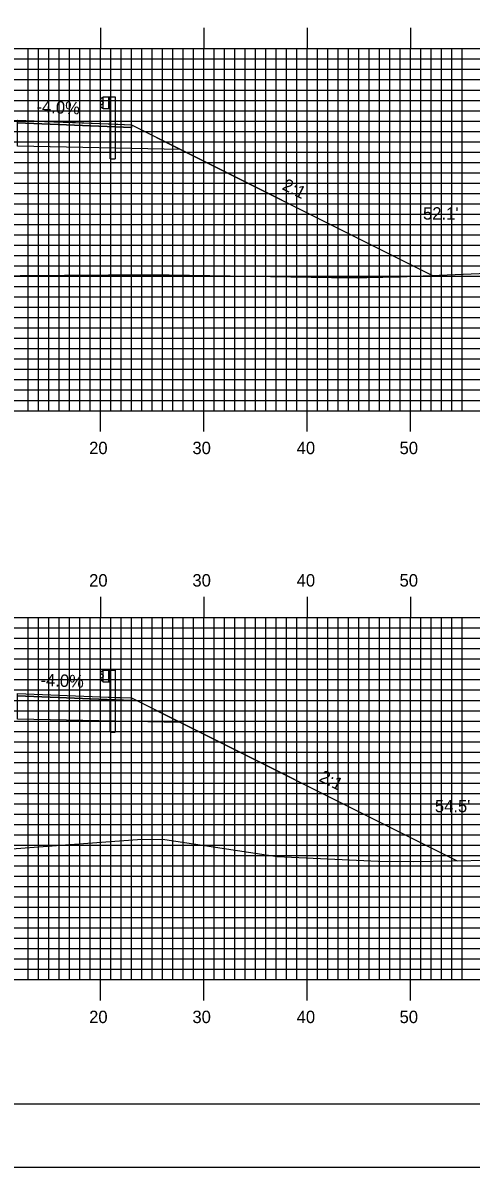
# Model space of a CAD drawing. Extents: x 1760610 to 1760954, y 442591 to 442811.
# Drawn here: x 1760788.7 to 1760832.1, y 442590.5 to 442701.2 of the extents above; entities that cross this region are included whole.
import ezdxf

# ---------------------------------------------------------------- set-up
doc = ezdxf.new("R2010")
doc.units = 0
for name, color, linetype in [('ANNOTATION', 7, 'Continuous'), ('BORDER', 7, 'Continuous'), ('D_Guardrail_Beam_Rt', 7, 'Continuous'), ('D_Roadway_Centerline', 7, 'Continuous'), ('D_Roadway_Edge_Shoulder', 7, 'Continuous'), ('D_Roadway_SlopeLines', 7, 'Continuous'), ('D_Roadway_SubGrade', 7, 'Continuous'), ('D_Text_Standard', 7, 'Continuous'), ('H_V ANNOTATION', 7, 'Continuous'), ('MAJOR', 7, 'Continuous'), ('MINOR', 7, 'Continuous'), ('PLOT BOUNDARY', 7, 'Continuous'), ('S_Roadway_Centerline', 7, 'Continuous')]:
    doc.layers.add(name, color=color, linetype=linetype)

msp = doc.modelspace()

# ---------------------------------------------------------------- linework, layer by layer
at = {"layer": 'BORDER'}
msp.add_lwpolyline([(1760626.61, 442596.67), (1760946.61, 442596.67), (1760946.61, 442806.67), (1760626.61, 442806.67)], close=True, dxfattribs=at)
at = {"layer": 'D_Guardrail_Beam_Rt'}
for p, q in [((1760796.39, 442693.91), (1760796.25, 442693.81)), ((1760796.48, 442693.93), (1760796.41, 442693.91)), ((1760796.48, 442694.01), (1760797.17, 442694.01)), ((1760796.48, 442692.84), (1760796.48, 442694.01)), ((1760797.01, 442694.01), (1760797.01, 442692.84)), ((1760797.11, 442694.01), (1760797.11, 442692.84)), ((1760797.17, 442694.01), (1760797.64, 442694.01)), ((1760797.17, 442694.01), (1760797.17, 442692.84)), ((1760797.64, 442694.01), (1760797.64, 442688.01)), ((1760796.25, 442693.66), (1760796.45, 442693.53)), ((1760796.45, 442693.33), (1760796.25, 442693.19)), ((1760796.25, 442693.05), (1760796.39, 442692.95)), ((1760796.41, 442692.94), (1760796.48, 442692.93)), ((1760796.48, 442693.46), (1760796.48, 442693.39)), ((1760797.17, 442692.84), (1760796.48, 442692.84)), ((1760797.15, 442688.01), (1760797.15, 442692.84)), ((1760797.15, 442688.01), (1760797.64, 442688.01)), ((1760796.39, 442638.5), (1760796.25, 442638.4)), ((1760796.48, 442638.52), (1760796.41, 442638.51)), ((1760796.48, 442638.6), (1760797.17, 442638.6)), ((1760796.48, 442637.44), (1760796.48, 442638.6)), ((1760797.01, 442638.6), (1760797.01, 442637.44)), ((1760797.11, 442638.6), (1760797.11, 442637.44)), ((1760797.17, 442638.6), (1760797.64, 442638.6)), ((1760797.17, 442638.6), (1760797.17, 442637.44)), ((1760797.64, 442638.6), (1760797.64, 442632.6)), ((1760796.25, 442638.26), (1760796.45, 442638.12)), ((1760796.45, 442637.92), (1760796.25, 442637.79)), ((1760796.25, 442637.64), (1760796.39, 442637.54)), ((1760796.41, 442637.54), (1760796.48, 442637.52)), ((1760796.48, 442638.06), (1760796.48, 442637.99)), ((1760797.17, 442637.44), (1760796.48, 442637.44)), ((1760797.15, 442632.6), (1760797.15, 442637.44)), ((1760797.15, 442632.6), (1760797.64, 442632.6))]:
    msp.add_line(p, q, dxfattribs=at)
for centre, major_axis, start_param, end_param in [((1760796.3, 442693.73), (-0.0877, 0), 5.323254, 7.243116), ((1760796.42, 442693.87), (-0.0417, 0), 4.907132, 5.323254), ((1760796.3, 442693.12), (-0.0877, 0), 5.323254, 7.243116), ((1760796.42, 442692.98), (-0.0417, 0), 0.959931, 1.376053), ((1760796.4, 442693.46), (0.0789, 0), 0, 0.959931), ((1760796.4, 442693.39), (0.0789, 0), 5.323254, 6.283185), ((1760796.42, 442638.47), (-0.0417, 0), 4.907132, 5.323254), ((1760796.3, 442638.33), (-0.0877, 0), 5.323254, 7.243116), ((1760796.3, 442637.71), (-0.0877, 0), 5.323254, 7.243116), ((1760796.42, 442637.58), (-0.0417, 0), 0.959931, 1.376053), ((1760796.4, 442638.06), (0.0789, 0), 0, 0.959931), ((1760796.4, 442637.99), (0.0789, 0), 5.323254, 6.283185)]:
    msp.add_ellipse(centre, major_axis=major_axis, ratio=0.995501, start_param=start_param, end_param=end_param, dxfattribs=at)
at = {"layer": 'D_Roadway_Centerline'}
for points in [[(1760723.62, 442675.65), (1760747.92, 442687.8), (1760747.92, 442687.8), (1760749.52, 442688.6), (1760753.21, 442690.44), (1760753.22, 442690.44), (1760756.21, 442690.56), (1760756.22, 442690.56), (1760764.21, 442690.88), (1760764.23, 442690.88), (1760769.08, 442691.06), (1760776.21, 442691.32), (1760776.21, 442691.32), (1760784.04, 442691.6), (1760788.21, 442691.75), (1760788.22, 442691.75), (1760790.81, 442691.64), (1760796.21, 442691.43), (1760796.21, 442691.43), (1760797.9, 442691.36), (1760799.21, 442691.31), (1760803.96, 442688.93), (1760828.33, 442676.75), (1760828.33, 442676.75)], [(1760788.21, 442636.34), (1760789.01, 442636.31), (1760796.21, 442636.02), (1760797.7, 442635.96), (1760799.21, 442635.9), (1760803.58, 442633.72), (1760803.96, 442633.53), (1760822.99, 442624.02), (1760830.72, 442620.15)]]:
    msp.add_lwpolyline(points, dxfattribs=at)
at = {"layer": 'D_Roadway_Edge_Shoulder'}
for points in [[(1760788.21, 442691.75), (1760796.21, 442691.43), (1760796.21, 442691.43), (1760799.21, 442691.31), (1760799.21, 442691.06), (1760788.21, 442691.5)], [(1760788.21, 442636.34), (1760796.21, 442636.02), (1760796.21, 442636.02), (1760799.21, 442635.9), (1760799.21, 442635.65), (1760788.21, 442636.09)]]:
    msp.add_lwpolyline(points, close=True, dxfattribs=at)
at = {"layer": 'D_Roadway_SlopeLines'}
for points in [[(1760799.21, 442691.31), (1760828.33, 442676.75)], [(1760799.21, 442635.9), (1760830.72, 442620.15)]]:
    msp.add_lwpolyline(points, dxfattribs=at)
at = {"layer": 'D_Roadway_SubGrade'}
for points in [[(1760788.21, 442691.08), (1760788.21, 442691.5), (1760799.21, 442691.06), (1760799.21, 442691.31), (1760803.96, 442688.93), (1760788.21, 442689.25)], [(1760788.21, 442635.68), (1760788.21, 442636.09), (1760799.21, 442635.65), (1760799.21, 442635.9), (1760803.96, 442633.53), (1760788.21, 442633.84)]]:
    msp.add_lwpolyline(points, close=True, dxfattribs=at)
at = {"layer": 'MAJOR'}
for p, q in [((1760796.21, 442700.67), (1760796.21, 442698.67)), ((1760806.21, 442700.67), (1760806.21, 442698.67)), ((1760816.21, 442700.67), (1760816.21, 442698.67)), ((1760826.21, 442700.67), (1760826.21, 442698.67)), ((1760636.21, 442698.67), (1760916.21, 442698.67)), ((1760636.21, 442698.67), (1760916.21, 442698.67)), ((1760796.21, 442663.67), (1760796.21, 442698.67)), ((1760806.21, 442663.67), (1760806.21, 442698.67)), ((1760816.21, 442663.67), (1760816.21, 442698.67)), ((1760826.21, 442663.67), (1760826.21, 442698.67)), ((1760636.21, 442693.67), (1760916.21, 442693.67)), ((1760636.21, 442688.67), (1760916.21, 442688.67)), ((1760636.21, 442683.67), (1760916.21, 442683.67)), ((1760636.21, 442678.67), (1760916.21, 442678.67)), ((1760636.21, 442673.67), (1760916.21, 442673.67)), ((1760636.21, 442668.67), (1760916.21, 442668.67)), ((1760636.21, 442663.67), (1760916.21, 442663.67)), ((1760636.21, 442663.67), (1760916.21, 442663.67)), ((1760796.21, 442661.66), (1760796.21, 442663.67)), ((1760806.21, 442661.66), (1760806.21, 442663.67)), ((1760816.21, 442661.66), (1760816.21, 442663.67)), ((1760826.21, 442661.66), (1760826.21, 442663.67)), ((1760796.21, 442645.67), (1760796.21, 442643.67)), ((1760806.21, 442645.67), (1760806.21, 442643.67)), ((1760816.21, 442645.67), (1760816.21, 442643.67)), ((1760826.21, 442645.67), (1760826.21, 442643.67)), ((1760636.21, 442643.67), (1760916.21, 442643.67)), ((1760636.21, 442643.67), (1760916.21, 442643.67)), ((1760796.21, 442608.67), (1760796.21, 442643.67)), ((1760806.21, 442608.67), (1760806.21, 442643.67)), ((1760816.21, 442608.67), (1760816.21, 442643.67)), ((1760826.21, 442608.67), (1760826.21, 442643.67)), ((1760636.21, 442638.67), (1760916.21, 442638.67)), ((1760636.21, 442633.67), (1760916.21, 442633.67)), ((1760636.21, 442628.67), (1760916.21, 442628.67)), ((1760636.21, 442623.67), (1760916.21, 442623.67)), ((1760636.21, 442618.67), (1760916.21, 442618.67)), ((1760636.21, 442613.67), (1760916.21, 442613.67)), ((1760636.21, 442608.67), (1760916.21, 442608.67)), ((1760636.21, 442608.67), (1760916.21, 442608.67)), ((1760796.21, 442606.66), (1760796.21, 442608.67)), ((1760806.21, 442606.66), (1760806.21, 442608.67)), ((1760816.21, 442606.66), (1760816.21, 442608.67)), ((1760826.21, 442606.66), (1760826.21, 442608.67))]:
    msp.add_line(p, q, dxfattribs=at)
at = {"layer": 'MINOR'}
for p, q in [((1760789.21, 442663.67), (1760789.21, 442698.67)), ((1760790.21, 442663.67), (1760790.21, 442698.67)), ((1760791.21, 442663.67), (1760791.21, 442698.67)), ((1760792.21, 442663.67), (1760792.21, 442698.67)), ((1760793.21, 442663.67), (1760793.21, 442698.67)), ((1760794.21, 442663.67), (1760794.21, 442698.67)), ((1760795.21, 442663.67), (1760795.21, 442698.67)), ((1760797.21, 442663.67), (1760797.21, 442698.67)), ((1760798.21, 442663.67), (1760798.21, 442698.67)), ((1760799.21, 442663.67), (1760799.21, 442698.67)), ((1760800.21, 442663.67), (1760800.21, 442698.67)), ((1760801.21, 442663.67), (1760801.21, 442698.67)), ((1760802.21, 442663.67), (1760802.21, 442698.67)), ((1760803.21, 442663.67), (1760803.21, 442698.67)), ((1760804.21, 442663.67), (1760804.21, 442698.67)), ((1760805.21, 442663.67), (1760805.21, 442698.67)), ((1760807.21, 442663.67), (1760807.21, 442698.67)), ((1760808.21, 442663.67), (1760808.21, 442698.67)), ((1760809.21, 442663.67), (1760809.21, 442698.67)), ((1760810.21, 442663.67), (1760810.21, 442698.67)), ((1760811.21, 442663.67), (1760811.21, 442698.67)), ((1760812.21, 442663.67), (1760812.21, 442698.67)), ((1760813.21, 442663.67), (1760813.21, 442698.67)), ((1760814.21, 442663.67), (1760814.21, 442698.67)), ((1760815.21, 442663.67), (1760815.21, 442698.67)), ((1760817.21, 442663.67), (1760817.21, 442698.67)), ((1760818.21, 442663.67), (1760818.21, 442698.67)), ((1760819.21, 442663.67), (1760819.21, 442698.67)), ((1760820.21, 442663.67), (1760820.21, 442698.67)), ((1760821.21, 442663.67), (1760821.21, 442698.67)), ((1760822.21, 442663.67), (1760822.21, 442698.67)), ((1760823.21, 442663.67), (1760823.21, 442698.67)), ((1760824.21, 442663.67), (1760824.21, 442698.67)), ((1760825.21, 442663.67), (1760825.21, 442698.67)), ((1760827.21, 442663.67), (1760827.21, 442698.67)), ((1760828.21, 442663.67), (1760828.21, 442698.67)), ((1760829.21, 442663.67), (1760829.21, 442698.67)), ((1760830.21, 442663.67), (1760830.21, 442698.67)), ((1760831.21, 442663.67), (1760831.21, 442698.67)), ((1760636.21, 442697.67), (1760916.21, 442697.67)), ((1760636.21, 442696.67), (1760916.21, 442696.67)), ((1760636.21, 442695.67), (1760916.21, 442695.67)), ((1760636.21, 442694.67), (1760916.21, 442694.67)), ((1760636.21, 442692.67), (1760916.21, 442692.67)), ((1760636.21, 442691.67), (1760916.21, 442691.67)), ((1760636.21, 442690.67), (1760916.21, 442690.67)), ((1760636.21, 442689.67), (1760916.21, 442689.67)), ((1760636.21, 442687.67), (1760916.21, 442687.67)), ((1760636.21, 442686.67), (1760916.21, 442686.67)), ((1760636.21, 442685.67), (1760916.21, 442685.67)), ((1760636.21, 442684.67), (1760916.21, 442684.67)), ((1760636.21, 442682.67), (1760916.21, 442682.67)), ((1760636.21, 442681.67), (1760916.21, 442681.67)), ((1760636.21, 442680.67), (1760916.21, 442680.67)), ((1760636.21, 442679.67), (1760916.21, 442679.67)), ((1760636.21, 442677.67), (1760916.21, 442677.67)), ((1760636.21, 442676.67), (1760916.21, 442676.67)), ((1760636.21, 442675.67), (1760916.21, 442675.67)), ((1760636.21, 442674.67), (1760916.21, 442674.67)), ((1760636.21, 442672.67), (1760916.21, 442672.67)), ((1760636.21, 442671.67), (1760916.21, 442671.67)), ((1760636.21, 442670.67), (1760916.21, 442670.67)), ((1760636.21, 442669.67), (1760916.21, 442669.67)), ((1760636.21, 442667.67), (1760916.21, 442667.67)), ((1760636.21, 442666.67), (1760916.21, 442666.67)), ((1760636.21, 442665.67), (1760916.21, 442665.67)), ((1760636.21, 442664.67), (1760916.21, 442664.67)), ((1760789.21, 442608.67), (1760789.21, 442643.67)), ((1760790.21, 442608.67), (1760790.21, 442643.67)), ((1760791.21, 442608.67), (1760791.21, 442643.67)), ((1760792.21, 442608.67), (1760792.21, 442643.67)), ((1760793.21, 442608.67), (1760793.21, 442643.67)), ((1760794.21, 442608.67), (1760794.21, 442643.67)), ((1760795.21, 442608.67), (1760795.21, 442643.67)), ((1760797.21, 442608.67), (1760797.21, 442643.67)), ((1760798.21, 442608.67), (1760798.21, 442643.67)), ((1760799.21, 442608.67), (1760799.21, 442643.67)), ((1760800.21, 442608.67), (1760800.21, 442643.67)), ((1760801.21, 442608.67), (1760801.21, 442643.67)), ((1760802.21, 442608.67), (1760802.21, 442643.67)), ((1760803.21, 442608.67), (1760803.21, 442643.67)), ((1760804.21, 442608.67), (1760804.21, 442643.67)), ((1760805.21, 442608.67), (1760805.21, 442643.67)), ((1760807.21, 442608.67), (1760807.21, 442643.67)), ((1760808.21, 442608.67), (1760808.21, 442643.67)), ((1760809.21, 442608.67), (1760809.21, 442643.67)), ((1760810.21, 442608.67), (1760810.21, 442643.67)), ((1760811.21, 442608.67), (1760811.21, 442643.67)), ((1760812.21, 442608.67), (1760812.21, 442643.67)), ((1760813.21, 442608.67), (1760813.21, 442643.67)), ((1760814.21, 442608.67), (1760814.21, 442643.67)), ((1760815.21, 442608.67), (1760815.21, 442643.67)), ((1760817.21, 442608.67), (1760817.21, 442643.67)), ((1760818.21, 442608.67), (1760818.21, 442643.67)), ((1760819.21, 442608.67), (1760819.21, 442643.67)), ((1760820.21, 442608.67), (1760820.21, 442643.67)), ((1760821.21, 442608.67), (1760821.21, 442643.67)), ((1760822.21, 442608.67), (1760822.21, 442643.67)), ((1760823.21, 442608.67), (1760823.21, 442643.67)), ((1760824.21, 442608.67), (1760824.21, 442643.67)), ((1760825.21, 442608.67), (1760825.21, 442643.67)), ((1760827.21, 442608.67), (1760827.21, 442643.67)), ((1760828.21, 442608.67), (1760828.21, 442643.67)), ((1760829.21, 442608.67), (1760829.21, 442643.67)), ((1760830.21, 442608.67), (1760830.21, 442643.67)), ((1760831.21, 442608.67), (1760831.21, 442643.67)), ((1760636.21, 442642.67), (1760916.21, 442642.67)), ((1760636.21, 442641.67), (1760916.21, 442641.67)), ((1760636.21, 442640.67), (1760916.21, 442640.67)), ((1760636.21, 442639.67), (1760916.21, 442639.67)), ((1760636.21, 442637.67), (1760916.21, 442637.67)), ((1760636.21, 442636.67), (1760916.21, 442636.67)), ((1760636.21, 442635.67), (1760916.21, 442635.67)), ((1760636.21, 442634.67), (1760916.21, 442634.67)), ((1760636.21, 442632.67), (1760916.21, 442632.67)), ((1760636.21, 442631.67), (1760916.21, 442631.67)), ((1760636.21, 442630.67), (1760916.21, 442630.67)), ((1760636.21, 442629.67), (1760916.21, 442629.67)), ((1760636.21, 442627.67), (1760916.21, 442627.67)), ((1760636.21, 442626.67), (1760916.21, 442626.67)), ((1760636.21, 442625.67), (1760916.21, 442625.67)), ((1760636.21, 442624.67), (1760916.21, 442624.67)), ((1760636.21, 442622.67), (1760916.21, 442622.67)), ((1760636.21, 442621.67), (1760916.21, 442621.67)), ((1760636.21, 442620.67), (1760916.21, 442620.67)), ((1760636.21, 442619.67), (1760916.21, 442619.67)), ((1760636.21, 442617.67), (1760916.21, 442617.67)), ((1760636.21, 442616.67), (1760916.21, 442616.67)), ((1760636.21, 442615.67), (1760916.21, 442615.67)), ((1760636.21, 442614.67), (1760916.21, 442614.67)), ((1760636.21, 442612.67), (1760916.21, 442612.67)), ((1760636.21, 442611.67), (1760916.21, 442611.67)), ((1760636.21, 442610.67), (1760916.21, 442610.67)), ((1760636.21, 442609.67), (1760916.21, 442609.67))]:
    msp.add_line(p, q, dxfattribs=at)
at = {"layer": 'PLOT BOUNDARY'}
msp.add_lwpolyline([(1760610.43, 442590.55), (1760950.43, 442590.55), (1760950.43, 442810.55), (1760610.43, 442810.55)], close=True, dxfattribs=at)
at = {"layer": 'S_Roadway_Centerline'}
for points in [[(1760711.92, 442675.53), (1760730.31, 442675.71), (1760734.82, 442675.73), (1760741.47, 442675.95), (1760750.12, 442676), (1760754.25, 442676.03), (1760757.6, 442676.1), (1760772.92, 442676.54), (1760780.57, 442676.71), (1760788.45, 442676.73), (1760796.99, 442676.8), (1760802.85, 442676.8), (1760818.56, 442676.53), (1760821.97, 442676.54), (1760825.1, 442676.61), (1760834.38, 442677.01)], [(1760711.14, 442619.36), (1760729.61, 442619.74), (1760733.29, 442619.76), (1760743.51, 442619.94), (1760754.29, 442620.03), (1760755.8, 442620.05), (1760766.86, 442620.28), (1760778.13, 442620.62), (1760778.5, 442620.63), (1760800.23, 442622.24), (1760802.43, 442622.22), (1760813.3, 442620.56), (1760823.06, 442620.13), (1760826.5, 442620.08), (1760845.03, 442620.4)]]:
    msp.add_lwpolyline(points, dxfattribs=at)

# ---------------------------------------------------------------- texts
at = {"layer": 'ANNOTATION'}
for s, rotation, p in [('-4.0%', 357.7095, (1760790.01, 442692.48)), ('2:1', 333.434, (1760813.7, 442685.1)), ('-4.0%', 357.7093, (1760790.4, 442637.06)), ('2:1', 333.4365, (1760817.27, 442627.91))]:
    msp.add_text(s, height=1.2, rotation=rotation, dxfattribs=at).set_placement(p)
at = {"layer": 'D_Text_Standard'}
for s, p in [("52.1'", (1760827.41, 442682.14)), ("54.5'", (1760828.56, 442624.85))]:
    msp.add_text(s, height=1.2, dxfattribs=at).set_placement(p)
at = {"layer": 'H_V ANNOTATION'}
for s, p in [('20', (1760795.12, 442659.47)), ('30', (1760805.11, 442659.47)), ('40', (1760815.19, 442659.47)), ('50', (1760825.14, 442659.47)), ('20', (1760795.12, 442646.67)), ('30', (1760805.11, 442646.67)), ('40', (1760815.19, 442646.67)), ('50', (1760825.14, 442646.67)), ('20', (1760795.12, 442604.47)), ('30', (1760805.11, 442604.47)), ('40', (1760815.19, 442604.47)), ('50', (1760825.14, 442604.47))]:
    msp.add_text(s, height=1.2, dxfattribs=at).set_placement(p)

doc.saveas('drawing.dxf')
